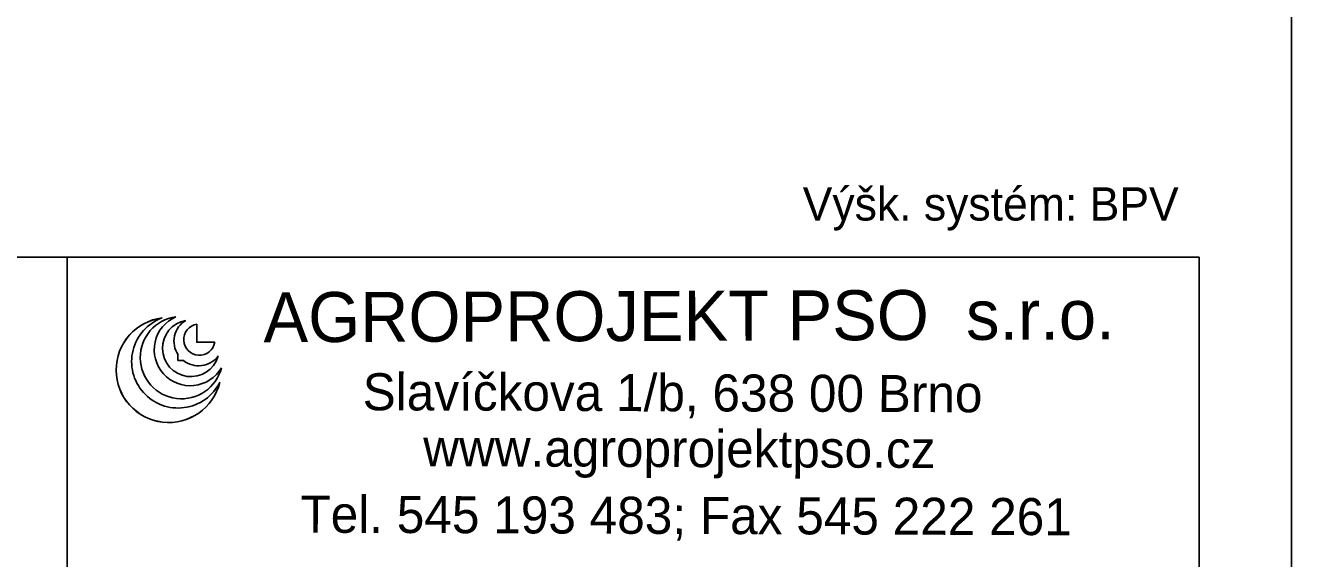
# Model space of a CAD drawing. Extents: x -553158.6 to -553137.6, y -1027695 to -1027665.3.
# Drawn here: x -553144.45 to -553137.61, y -1027690.01 to -1027687.13 of the extents above; entities that cross this region are included whole.
import ezdxf

# ---------------------------------------------------------------- set-up
doc = ezdxf.new("R2010")
doc.units = 0
doc.layers.add('Implicitní', color=7, linetype='Continuous')
doc.layers.add('rámeček', color=7, linetype='Continuous')

# ---------------------------------------------------------------- blocks, each defined once
blk = doc.blocks.new('A$C038E1F8A')
at = {"layer": 'Implicitní'}
blk.add_line((0, 0.297), (0, 0), dxfattribs=at)

msp = doc.modelspace()

# ---------------------------------------------------------------- linework, layer by layer
at = {"layer": 'rámeček'}
for p, q in [((-553153.6106, -1027688.3833), (-553138.1106, -1027688.3833)), ((-553144.2207, -1027694.5383), (-553144.2207, -1027688.3833)), ((-553138.1106, -1027694.5383), (-553138.1106, -1027688.3833))]:
    msp.add_line(p, q, dxfattribs=at)
for points in [[(-553143.4234, -1027688.8431), (-553143.5203, -1027688.8427), (-553143.52, -1027688.7455), (-553143.5199, -1027688.7455)], [(-553143.5927, -1027688.942), (-553143.6218, -1027688.9419), (-553143.6217, -1027688.9104)], [(-553143.4058, -1027688.9185), (-553143.4055, -1027688.9176)]]:
    msp.add_lwpolyline(points, dxfattribs=at)
for centre, radius, start, end in [((-553143.6027, -1027688.9254), 0.2226, 97.81745, 263.10364), ((-553143.5553, -1027688.8831), 0.1943, 113.54921, 221.7815), ((-553143.6719, -1027688.9924), 0.2834, 97.10191, 263.33083), ((-553143.672, -1027688.9926), 0.2834, 97.10191, 263.33083), ((-553143.621, -1027688.947), 0.2509, 110.06189, 221.77285), ((-553143.5526, -1027688.8753), 0.1531, 99.98322, 262.38407), ((-553143.511, -1027688.8379), 0.1323, 120.99931, 213.23852), ((-553143.5065, -1027688.8287), 0.0843, 99.17763, 182.85043), ((-553143.5065, -1027688.8287), 0.0843, 182.85103, 266.52503), ((-553143.5065, -1027688.8287), 0.0843, 266.52663, 350.20062), ((-553143.5553, -1027688.8831), 0.1943, 221.78162, 330.01391), ((-553143.6027, -1027688.9254), 0.2226, 263.10389, 345.74666), ((-553143.511, -1027688.8379), 0.1323, 231.91163, 322.92601), ((-553143.5526, -1027688.8753), 0.1531, 262.38407, 343.5864), ((-553143.621, -1027688.947), 0.2509, 221.77288, 333.48505), ((-553143.6719, -1027688.9924), 0.2834, 263.33109, 346.44555), ((-553143.672, -1027688.9926), 0.2834, 263.33109, 346.44555)]:
    msp.add_arc(centre, radius, start, end, dxfattribs=at)

# ---------------------------------------------------------------- block references
at = {"layer": 'Implicitní', "xscale": 100, "yscale": 100}
msp.add_blockref('A$C038E1F8A', (-553137.6106, -1027695.0383), dxfattribs=at)

# ---------------------------------------------------------------- texts
at = {"layer": 'rámeček'}
for s, height, rotation, p in [('Výšk. systém: BPV', 0.17971, 0, (-553140.2499, -1027688.1854)), ('AGROPROJEKT PSO  s.r.o.', 0.27, 0.193, (-553143.1597, -1027688.8427)), ('Slavíčkova 1/b, 638 00 Brno', 0.2, 359.80619, (-553142.6251, -1027689.2098)), ('www.agroprojektpso.cz', 0.2, 359.80619, (-553142.2983, -1027689.5121)), ('Tel. 545 193 483; Fax 545 222 261', 0.2, 359.80619, (-553142.9611, -1027689.8709))]:
    msp.add_text(s, height=height, rotation=rotation, dxfattribs=at).set_placement(p)

doc.saveas('drawing.dxf')
